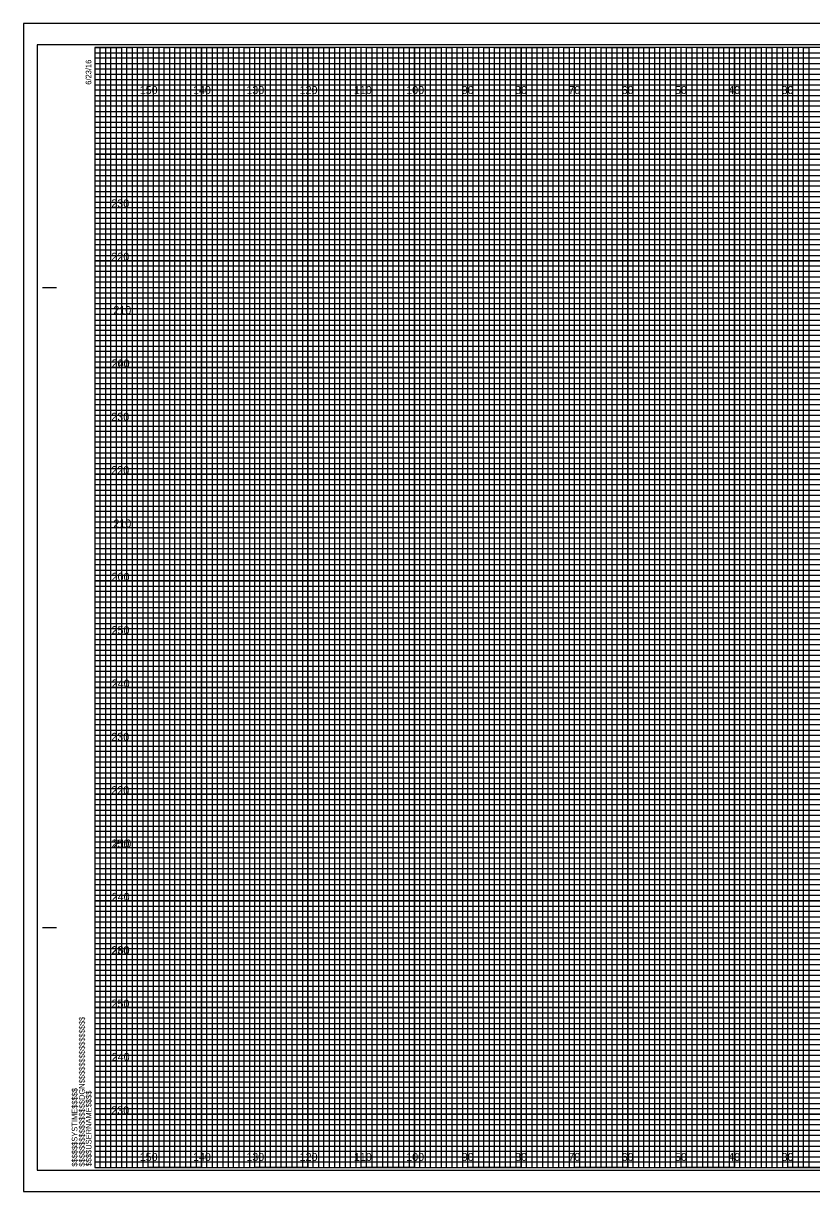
# Model space of a CAD drawing. Extents: x -13 to 359, y -5 to 2854.
# Drawn here: x -13.4 to 134.5, y 875.5 to 1094.5 of the extents above; entities that cross this region are included whole.
import ezdxf

# ---------------------------------------------------------------- set-up
doc = ezdxf.new("R2010")
doc.units = 0
for name, color, linetype in [('Exist Cross Section Cell', 7, 'Continuous'), ('Exist XS Ground Line', 7, 'Continuous'), ('Prop CMT Concrete Structures', 7, 'Continuous'), ('Prop CMT DNC', 7, 'Continuous'), ('Prop CMT Pvmt Course 1', 7, 'Continuous'), ('Prop CMT Pvmt Course 1 CG', 7, 'Continuous'), ('Prop CMT Pvmt Course 2', 7, 'Continuous'), ('Prop CMT Shear Line', 7, 'Continuous'), ('Prop CMT Slope Grass', 7, 'Continuous'), ('Prop CMT Subgrade Earthwork', 7, 'Continuous'), ('Scratch_Level_0', 7, 'Continuous')]:
    doc.layers.add(name, color=color, linetype=linetype)

msp = doc.modelspace()

# ---------------------------------------------------------------- linework, layer by layer
at = {"layer": 'Exist XS Ground Line'}
for p, q in [((10, 1090), (0, 1090)), ((10, 880), (10, 1090)), ((30, 1090), (20, 1090)), ((20, 1090), (20, 880)), ((30, 880), (30, 1090)), ((50, 1090), (40, 1090)), ((40, 1090), (40, 880)), ((50, 880), (50, 1090)), ((70, 1090), (60, 1090)), ((60, 1090), (60, 880)), ((70, 880), (70, 1090)), ((90, 1090), (80, 1090)), ((80, 1090), (80, 880)), ((90, 880), (90, 1090)), ((110, 1090), (100, 1090)), ((100, 1090), (100, 880)), ((110, 880), (110, 1090)), ((130, 1090), (120, 1090)), ((120, 1090), (120, 880)), ((130, 880), (130, 1090)), ((20, 880), (10, 880)), ((40, 880), (30, 880)), ((60, 880), (50, 880)), ((80, 880), (70, 880)), ((100, 880), (90, 880)), ((120, 880), (110, 880)), ((140, 880), (130, 880))]:
    msp.add_line(p, q, dxfattribs=at)
for points in [[(0, 1080), (320, 1080), (320, 1070), (0, 1070)], [(0, 1060), (320, 1060), (320, 1050), (0, 1050)], [(0, 1040), (320, 1040), (320, 1030), (0, 1030)], [(0, 1020), (320, 1020), (320, 1010), (0, 1010)], [(0, 1000), (320, 1000), (320, 990), (0, 990)], [(0, 980), (320, 980), (320, 970), (0, 970)], [(0, 960), (320, 960), (320, 950), (0, 950)], [(0, 940), (320, 940), (320, 930), (0, 930)], [(0, 920), (320, 920), (320, 910), (0, 910)], [(0, 900), (320, 900), (320, 890), (0, 890)]]:
    msp.add_lwpolyline(points, dxfattribs=at)
at = {"layer": 'Prop CMT Concrete Structures'}
for p, q in [((-9.8, 1045), (-7.3, 1045)), ((-9.7, 1045), (-7.2, 1045)), ((-9.8, 925), (-7.3, 925)), ((-9.7, 925), (-7.2, 925)), ((0, 880), (0, 880)), ((0, 880), (0, 880)), ((0, 880), (0, 880)), ((0, 880), (0, 880)), ((0, 880), (0, 880)), ((0, 880), (0, 880)), ((0, 880), (0, 880))]:
    msp.add_line(p, q, dxfattribs=at)
msp.add_lwpolyline([(320, 1090), (0, 1090), (0, 880), (320, 880)], close=True, dxfattribs=at)
at = {"layer": 'Prop CMT DNC'}
for p, q in [((323.3, 1094.5), (-13.4, 1094.5)), ((-13.4, 1094.5), (-13.4, 875.5)), ((-13.4, 875.5), (323.3, 875.5))]:
    msp.add_line(p, q, dxfattribs=at)
at = {"layer": 'Prop CMT Pvmt Course 1'}
for p, q in [((0, 1089), (260, 1089)), ((260, 1087.98), (0, 1087.98)), ((0, 1087.98), (0, 1087)), ((0, 1087), (260, 1087)), ((260, 1085.89), (0, 1085.89)), ((0, 1085.89), (0, 1084)), ((0, 1084), (320, 1084))]:
    msp.add_line(p, q, dxfattribs=at)
for points in [[(0, 1083), (270, 1083), (320, 1083), (320, 1082), (0, 1082)], [(0, 1081), (320, 1081), (320, 1079), (0, 1079)], [(0, 1078), (320, 1078), (320, 1077), (0, 1076.98)], [(0, 1076), (320, 1076), (320, 1074), (0, 1074)], [(0, 1073), (320, 1073), (320, 1072), (0, 1072)], [(0, 1071), (320, 1071), (320, 1069), (0, 1069)], [(0, 1068), (320, 1068), (320, 1067), (0, 1067)], [(0, 1066), (320, 1066), (320, 1064), (0, 1064)], [(0, 1063), (320, 1063), (320, 1062), (0, 1062)], [(0, 1061), (320, 1061), (320, 1059), (0, 1059)], [(0, 1058), (320, 1058), (320, 1057), (0, 1057)], [(0, 1056), (320, 1056), (320, 1053.95), (320, 1053), (320, 1052), (0, 1052)], [(0, 1054), (320, 1054), (320, 1053), (0, 1053)], [(0, 1051), (320, 1051), (320, 1049), (0, 1049.03)], [(0, 1049.03), (320, 1049), (320, 1048), (0, 1048)], [(0, 1047), (320, 1047), (320, 1046), (0, 1046)], [(0, 1044), (320, 1044), (320, 1043), (0, 1043)], [(0, 1042), (320, 1042), (320, 1041), (0, 1041)], [(-0.07, 1038.89), (320, 1038.89), (320, 1037.88), (-0.07, 1037.88)], [(0, 1037), (320, 1037), (320, 1036), (0, 1036)], [(0, 1034), (320, 1034), (320, 1033), (0, 1033)], [(0, 1032), (320, 1032), (320, 1031), (0, 1031)], [(0, 1029), (320, 1029), (320, 1028), (0, 1028)], [(0, 1027), (320, 1027), (320, 1026), (0, 1026)], [(0, 1024), (320, 1024), (320, 1023), (0, 1023)], [(0, 1022), (320, 1022), (320, 1021), (0, 1021)], [(0, 1019), (320, 1019), (319.99, 1017.98), (0, 1018)], [(0, 1017), (320, 1017), (320, 1016), (0, 1016)], [(0, 1014), (320, 1014), (320, 1013), (0, 1013)], [(0, 1012), (320, 1012), (320, 1011), (0, 1011)], [(0, 1009), (320, 1009), (320, 1008), (0, 1008)], [(0, 1007), (320, 1007), (320, 1006), (0, 1006)], [(0, 1004), (320, 1004), (320, 1003), (0, 1003)], [(0, 1002), (320, 1002), (320, 1001), (0, 1001)], [(0, 999), (320, 999), (320, 998), (0, 998)], [(0, 996.99), (320.07, 996.91), (320, 996), (0, 996)], [(0, 994), (320, 994), (320, 993), (0, 993)], [(0, 992), (320, 992), (320, 991), (0, 991)], [(0, 989), (320, 989), (320, 988), (0, 988)], [(0, 987), (320, 987), (320, 986), (0, 986)], [(0, 984), (320, 984), (320, 983), (0, 983)], [(0, 982), (320, 982), (320, 981), (0, 981)], [(0, 979), (320, 979), (320, 978), (0, 978)], [(0, 977), (320, 977), (320, 976), (0, 976)], [(0, 974), (320, 974), (320, 973), (0, 973)], [(0, 972), (320, 972), (320, 971), (0, 971)], [(0, 969), (320, 969), (320, 968), (0, 968)], [(0, 967), (320, 967), (320, 966), (0, 966)], [(0, 964), (320, 964), (320, 963), (0, 963)], [(0, 962), (320, 962), (320, 961), (0, 961)], [(0, 959), (320, 959), (319.99, 957.98), (0, 958)], [(0, 957), (320, 957), (320, 956), (0, 956)], [(0, 954), (320, 954), (320, 953), (0, 953)], [(0, 952), (320, 952), (320, 951), (0, 951)], [(0, 949), (320, 949), (320, 948), (0, 948)], [(0, 947), (320, 947), (320, 946), (0, 946)], [(0, 944), (320, 944), (320, 943), (0, 943)], [(0, 942), (320, 942), (320, 941), (0, 941)], [(0, 939), (320, 939), (320, 938), (0, 938)], [(0, 936.99), (320.07, 936.91), (320, 936), (0, 936)], [(0, 934), (320, 934), (320, 933), (0, 933)], [(0, 932), (320, 932), (320, 931), (0, 931)], [(0, 929), (320, 929), (320, 928), (0, 928)], [(0, 927), (320, 927), (320, 926), (0, 926)], [(0, 924), (320, 924), (320, 923), (0, 923)], [(0, 922), (320, 922), (320, 921), (0, 921)], [(0, 919), (320, 919), (320, 918), (0, 918)], [(0, 917), (320, 917), (320, 916), (0, 916)], [(0, 914), (320, 914), (320, 913), (0, 913)], [(0, 912), (320, 912), (320, 911), (0, 911)], [(0, 909), (320, 909), (320, 908), (0, 908)], [(0, 907), (320, 907), (320, 906), (0, 906)], [(0, 904), (320, 904), (320, 903), (0, 903)], [(0, 902), (320, 902), (320, 901), (0, 901)], [(0, 899), (320, 899), (320, 898), (0, 898)], [(0, 897), (320, 897), (320, 896), (0, 896)], [(0, 894), (320, 894), (320, 893), (0, 893)], [(0, 892), (320, 892), (320, 891), (0, 891)], [(0, 889), (320, 889), (320, 888), (0, 888)], [(0, 887), (320, 887), (320, 886), (0, 886)], [(0, 884), (320, 884), (320, 883), (0, 883)], [(0, 882), (320, 882), (320, 881), (0, 881)]]:
    msp.add_lwpolyline(points, dxfattribs=at)
at = {"layer": 'Prop CMT Pvmt Course 1 CG'}
for points in [[(0, 880), (1, 880), (1, 1090), (2, 1090), (2, 880)], [(2, 880), (3, 880), (3, 1090), (4, 1090), (4, 880)], [(5, 880), (6, 880), (6, 1090), (7, 1090), (7, 880)], [(7, 880), (8, 880), (8, 1090), (9, 1090), (9, 880)], [(10, 880), (11, 880), (11, 1090), (12, 1090), (12, 880)], [(12, 880), (13, 880), (13, 1090), (14, 1090), (14, 880)], [(15, 880), (16, 880), (16, 1090), (17, 1090), (17, 880)], [(17, 880), (18, 880), (18, 1090), (19, 1090), (19, 880)], [(20, 880), (21, 880), (21, 1090), (22, 1090), (22, 880)], [(22, 880), (23, 880), (23, 1090), (24, 1090), (24, 880)], [(25, 880), (26, 880), (26, 1090), (27, 1090), (27, 880)], [(27, 880), (28, 880), (28, 1090), (29, 1090), (29, 880)], [(30, 880), (31, 880), (31, 1090), (32, 1090), (32, 880)], [(32, 880), (33, 880), (33, 1090), (34, 1090), (34, 880)], [(35, 880), (36, 880), (36, 1090), (37, 1090), (37, 880)], [(37, 880), (38, 880), (38, 1090), (39, 1090), (39, 880)], [(40, 880), (41, 880), (41, 1090), (42, 1090), (42, 880)], [(42, 880), (43, 880), (43, 1090), (44, 1090), (44, 880)], [(45, 880), (46, 880), (46, 1090), (47, 1090), (47, 880)], [(47, 880), (48, 880), (48, 1090), (49, 1090), (49, 880)], [(50, 880), (51, 880), (51, 1090), (52, 1090), (52, 880)], [(52, 880), (53, 880), (53, 1090), (54, 1090), (54, 880)], [(55, 880), (56, 880), (56, 1090), (57, 1090), (57, 880)], [(57, 880), (58, 880), (58, 1090), (59, 1090), (59, 880)], [(60, 880), (61, 880), (61, 1090), (62, 1090), (62, 880)], [(62, 880), (63, 880), (63, 1090), (64, 1090), (64, 880)], [(65, 880), (66, 880), (66, 1090), (67, 1090), (67, 880)], [(67, 880), (68, 880), (68, 1090), (69, 1090), (69, 880)], [(70, 880), (71, 880), (71, 1090), (72, 1090), (72, 880)], [(72, 880), (73, 880), (73, 1090), (74, 1090), (74, 880)], [(75, 880), (76, 880), (76, 1090), (77, 1090), (77, 880)], [(77, 880), (78, 880), (78, 1090), (79, 1090), (79, 880)], [(80, 880), (81, 880), (81, 1090), (82, 1090), (82, 880)], [(82, 880), (83, 880), (83, 1090), (84, 1090), (84, 880)], [(85, 880), (86, 880), (86, 1090), (87, 1090), (87, 880)], [(87, 880), (88, 880), (88, 1090), (89, 1090), (89, 880)], [(90, 880), (91, 880), (91, 1090), (92, 1090), (92, 880)], [(92, 880), (93, 880), (93, 1090), (94, 1090), (94, 880)], [(95, 880), (96, 880), (96, 1090), (97, 1090), (97, 880)], [(97, 880), (98, 880), (98, 1090), (99, 1090), (99, 880)], [(100, 880), (101, 880), (101, 1090), (102, 1090), (102, 880)], [(102, 880), (103, 880), (103, 1090), (104, 1090), (104, 880)], [(105, 880), (106, 880), (106, 1090), (107, 1090), (107, 880)], [(107, 880), (108, 880), (108, 1090), (109, 1090), (109, 880)], [(110, 880), (111, 880), (111, 1090), (112, 1090), (112, 880)], [(112, 880), (113, 880), (113, 1090), (114, 1090), (114, 880)], [(115, 880), (116, 880), (116, 1090), (117, 1090), (117, 880)], [(117, 880), (118, 880), (118, 1090), (119, 1090), (119, 880)], [(120, 880), (121, 880), (121, 1090), (122, 1090), (122, 880)], [(122, 880), (123, 880), (123, 1090), (124, 1090), (124, 880)], [(125, 880), (126, 880), (126, 1090), (127, 1090), (127, 880)], [(127, 880), (128, 880), (128, 1090), (129, 1090), (129, 880)], [(130, 880), (131, 880), (131, 1090), (132, 1090), (132, 880)], [(132, 880), (133, 880), (133, 1090), (134, 1090), (134, 880)]]:
    msp.add_lwpolyline(points, dxfattribs=at)
at = {"layer": 'Prop CMT Shear Line'}
for p, q in [((10, 880), (10, 1090)), ((20, 880), (20, 1090)), ((30, 880), (30, 1090)), ((40, 880), (40, 1090)), ((50, 880), (50, 1090)), ((60, 880), (60, 1090)), ((70, 880), (70, 1090)), ((80, 880), (80, 1090)), ((90, 880), (90, 1090)), ((100, 880), (100, 1090)), ((110, 880), (110, 1090)), ((120, 880), (120, 1090)), ((130, 880), (130, 1090)), ((0, 1080), (320, 1080)), ((0, 1070), (320, 1070)), ((0, 1060), (320, 1060)), ((0, 1050), (320, 1050)), ((0, 1040), (320, 1040)), ((0, 1030), (320, 1030)), ((0, 1020), (320, 1020)), ((0, 1010), (320, 1010)), ((0, 1000), (320, 1000)), ((0, 990), (320, 990)), ((0, 980), (320, 980)), ((0, 970), (320, 970)), ((0, 960), (320, 960)), ((0, 950), (320, 950)), ((0, 940), (320, 940)), ((0, 930), (320, 930)), ((0, 920), (320, 920)), ((0, 910), (320, 910)), ((0, 900), (320, 900)), ((0, 890), (320, 890))]:
    msp.add_line(p, q, dxfattribs=at)
at = {"layer": 'Prop CMT Slope Grass'}
msp.add_lwpolyline([(-10.8, 879.5), (322.4, 879.5), (322.4, 1090.5), (-10.8, 1090.5)], close=True, dxfattribs=at)
at = {"layer": 'Prop CMT Subgrade Earthwork'}
msp.add_lwpolyline([(-13.4, 875.5), (323.3, 875.5), (323.3, 1094.5), (-13.4, 1094.5)], close=True, dxfattribs=at)
at = {"layer": 'Scratch_Level_0'}
for points in [[(0, 1090), (5, 1090), (5, 880), (15, 880), (15, 1090), (25, 1090), (25, 880), (35, 880), (35, 1090), (45, 1090), (45, 880), (55, 880), (55, 1090), (65, 1090), (65, 880), (75, 880), (75, 1090), (85, 1090), (85, 880), (95, 880), (95, 1090), (105, 1090), (105, 880), (115, 880), (115, 1090), (125, 1090), (125, 880), (135, 880)], [(0, 1085), (275, 1085)], [(0, 1065), (320, 1065), (320, 1075), (0, 1075)], [(0, 1045), (320, 1045), (320, 1055), (0, 1055)], [(0, 1025), (320, 1025), (320, 1035), (0, 1035)], [(0, 1005), (320, 1005), (320, 1015), (0, 1015)], [(0, 985), (320, 985), (320, 995), (0, 995)], [(0, 965), (320, 965), (320, 975), (0, 975)], [(0, 945), (320, 945), (320, 955), (0, 955)], [(0, 925), (320, 925), (320, 935), (0, 935)], [(0, 905), (320, 905), (320, 915), (0, 915)], [(0, 885), (320, 885), (320, 895), (0, 895)]]:
    msp.add_lwpolyline(points, dxfattribs=at)

# ---------------------------------------------------------------- texts
at = {"layer": 'Exist Cross Section Cell'}
for s, p in [('150', (8.44, 1081.25)), ('140', (18.44, 1081.25)), ('130', (28.44, 1081.25)), ('120', (38.44, 1081.25)), ('110', (48.62, 1081.25)), ('100', (58.44, 1081.25)), ('90', (68.86, 1081.25)), ('80', (78.86, 1081.25)), ('70', (88.86, 1081.25)), ('60', (98.86, 1081.25)), ('50', (108.86, 1081.25)), ('40', (118.86, 1081.25)), ('30', (128.86, 1081.25)), ('150', (8.44, 881.25)), ('140', (18.44, 881.25)), ('130', (28.44, 881.25)), ('120', (38.44, 881.25)), ('110', (48.62, 881.25)), ('100', (58.44, 881.25)), ('90', (68.86, 881.25)), ('80', (78.86, 881.25)), ('70', (88.86, 881.25)), ('60', (98.86, 881.25)), ('50', (108.86, 881.25)), ('40', (118.86, 881.25)), ('30', (128.86, 881.25))]:
    msp.add_text(s, height=1.5, dxfattribs=at).set_placement(p)
at = {"layer": 'Prop CMT Concrete Structures'}
for s, p in [('6/23/16', (-0.65, 1083)), ('$$$$$$$$$$$$$$$$DGN$$$$$$$$$$$$$$$$', (-1.88, 880.18)), ('$$$$$$SYSTIME$$$$$', (-3.26, 880.18)), ('$$$$USERNAME$$$$', (-0.62, 880.23))]:
    msp.add_text(s, height=1.05, rotation=90, dxfattribs=at).set_placement(p)
at = {"layer": 'Prop CMT Pvmt Course 2'}
for s, p in [('230', (3.11, 1060)), ('220', (3.12, 1050)), ('210', (3.5, 1040)), ('200', (3.17, 1030)), ('240', (3.19, 1030)), ('230', (3.11, 1020)), ('220', (3.12, 1010)), ('210', (3.5, 1000)), ('200', (3.17, 990)), ('250', (3.15, 980)), ('240', (3.19, 970)), ('230', (3.11, 960)), ('220', (3.12, 950)), ('250', (3.15, 940)), ('210', (3.5, 940)), ('240', (3.19, 930)), ('230', (3.11, 920)), ('260', (3.19, 920)), ('250', (3.15, 910)), ('240', (3.19, 900)), ('230', (3.11, 890))]:
    msp.add_text(s, height=1.5, dxfattribs=at).set_placement(p)

doc.saveas('drawing.dxf')
